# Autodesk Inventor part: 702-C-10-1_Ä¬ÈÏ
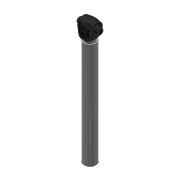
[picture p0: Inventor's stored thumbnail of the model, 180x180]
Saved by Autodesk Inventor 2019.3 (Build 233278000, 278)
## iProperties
Created: 2010-06
Part Number: 702-C-10-1_Ä¬ÈÏ
Material: Ogólny
Document SubType Name: Modeling
Designer: CADENGINEERING4
Density: 1 g/cm^3
Appearance: Gładki — czarny
Author: CADENGINEERING4
Revision Number: ÈÎºÎ
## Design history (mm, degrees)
node "NONE"
node "NONE:1"
node "Bryła1"
node "Bryła2"
